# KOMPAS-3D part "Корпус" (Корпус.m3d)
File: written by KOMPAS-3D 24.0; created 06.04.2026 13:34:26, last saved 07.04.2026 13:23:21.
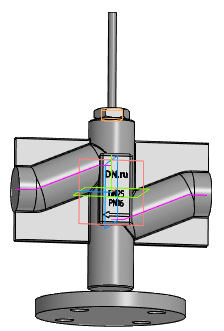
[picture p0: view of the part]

Document properties: Автор: R2D2; Полное имя файла: E:\Работа\Зайцев\Солянка\VSR1-13V-PED-F Клапан запорно-регулирующий DN.ru\DN25\исходные материалы\Корпус.m3d

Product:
- Body: Труба / Нестандартная труба / L = 79.1 мм  | qty 1
    Материал: Нестандартная труба (density 7856 kg/m3)
    Масса: 2.277391
    Раздел спецификации: Детали
    Примечание: 0,6 кг
    additional columns: Pipeline; 0.035; 0; 0; 0.002; 0.07905; true; 0.04
- Body: Труба / Нестандартная труба / L = 79.1 мм  | qty 1
    Материал: Нестандартная труба (density 7856 kg/m3)
    Масса: 2.277391
    Раздел спецификации: Детали
    Форматы листов документа: БЧ
    Примечание: 0,6 кг
    additional columns: Pipeline; 0.035; 0; 0; 0.002; 0.07905; true; 0.04
- Component [standard]: Гайка М16-6H ГОСТ 5916-70  | qty 1  | Масса: 0.01768; Рассекать на разрезах: no; source file: C:\Program Files\ASCON\KOMPAS-3D v24\Libs\PolynomLib\DATA\vault\Methods\Kompas\3D\PLib_Nut_OST92_900.m3d
- Component [standard]: (unnamed)  | qty 1  | Материал: ВЧ40 ГОСТ 7293-85 (density 7200 kg/m3); Масса: 0.904191; Рассекать на разрезах: no; additional columns: 25-16-B-1-ВЧ40-II; Заглушка; ГОСТ 34785-2021
- Body: Тело 4  | qty 1
    Материал: Нестандартная труба (density 7856 kg/m3)
    Масса: 2.277391
- Part/product: Корпус
    Масса: 6.9

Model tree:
1. Эскиз:1
2. Труба:1  (labels: {F703FF30-5BE6-4673-A7F1-8EDA1BE1E2D1}; SHAPEOBJECT3D_ATTR_BUTT; SHAPEOBJECT3D_ATTR_VALID; SHAPEOBJECT3D_ATTR_BUTT_AREA)
     PIPE_R = 7
3. Труба:2  (labels: {F703FF30-5BE6-4673-A7F1-8EDA1BE1E2D1}; SHAPEOBJECT3D_ATTR_BUTT; SHAPEOBJECT3D_ATTR_VALID; SHAPEOBJECT3D_ATTR_BUTT_AREA)
     PIPE_R = 7
4. Эскиз:2
5. Элемент выдавливания:1
     Расстояние 1 = 55; Смещение 1 = -1; Расстояние 2 = 75; Смещение 2 = -5
6. РЕБРО  (with: Ребро.Труба:2)
7. Элемент выдавливания:2
     Расстояние 1 = 6
8. Эскиз:4  (with: Грань.Элемент выдавливания:1)
9. Элемент выдавливания:3
     Расстояние 1 = 1
10. Эскиз:5  (with: Грань.Элемент выдавливания:3)
11. Элемент выдавливания:4
     Расстояние 1 = 7.5; Смещение 1 = 0.5
12. ШТОК
13. Элемент выдавливания:5
14. Скругление:3  (with: Ребро.Элемент выдавливания:2)
15. ОТЛИВКА
16. Скругление:6  (with: Грань.Элемент выдавливания:1)
17. Элемент выдавливания:6  (with: Грань.Элемент выдавливания:1)
     Смещение 1 = 4
18. Эскиз:8  (with: Грань.Элемент выдавливания:6)
19. Элемент выдавливания:7
     Расстояние 1 = 0.5
20. Скругление:7  (with: Ребро.Элемент выдавливания:6)
     Радиус = 2
21. Скругление:8  (with: Ребро.Элемент выдавливания:6, Грань.Элемент выдавливания:3, Грань.Элемент выдавливания:1)
     Радиус = 2

Expressions: DS/2+3
Referenced files in C:\Program Files\ASCON\KOMPAS-3D v24\Libs\Pipeline\: StylesTemplate.a3d, TemplateHPH, InsulationStylesTemplate.a3d, Insulation
Referenced files in C:\Program Files\ASCON\KOMPAS-3D v24\Templates\: Констр. чертеж А3 гориз. перв. лист.cdt
Referenced files in E:\Работа\Зайцев\Солянка\VSR1-13V-PED-F Клапан запорно-регулирующий DN.ru\DN15\DN15 Kv0.16\исходные материалы\: 
Referenced files in C:\Program Files\ASCON\KOMPAS-3D v24\Libs\PolynomLib\DATA\vault\Methods\Kompas\3D\: PLib_Nut_OST92_900.m3d, PLib_Flange_Blind_GOST_34785_2100.m3d
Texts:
  Отводы ГОСТ 17375-2001
  Констр. чертеж А3 гориз. перв. лист.cdt
  BOSimple***PART:2c8e7818-1586-f79e-db7d-bc045ba468e4***SHORTLOC:Root±30±10±20±©{}110±10±50±80[Нет;Без покрытия;Без указания материала;-;16;2;24]
  BOSimple***Material:38d6725a-5efe-48e1-b177-a7817acb862a
  BOSimple***PART:d2a51a88-948e-a384-3928-52a4aa3349e8***SHORTLOC:B619_EF039B503CC34112[1;16;25;Круглая;II;ВЧ40 ГОСТ 7293-85]
  var3D
  GOST 2.304 type A
  PN16
  DN+10
  LL-10
  bcut1
  hole1
  hcut1
  hole2
  cut1
  Труба / Нестандартная труба / L = %s мм
  Plane. Начало координат
  Плоскость ZX.Начало координат
  Ось Y.Начало координат
  Плоскость ZY.Начало координат
  Горизонтальная плоскость. Начало координат
  Плоскость XY.Начало координат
